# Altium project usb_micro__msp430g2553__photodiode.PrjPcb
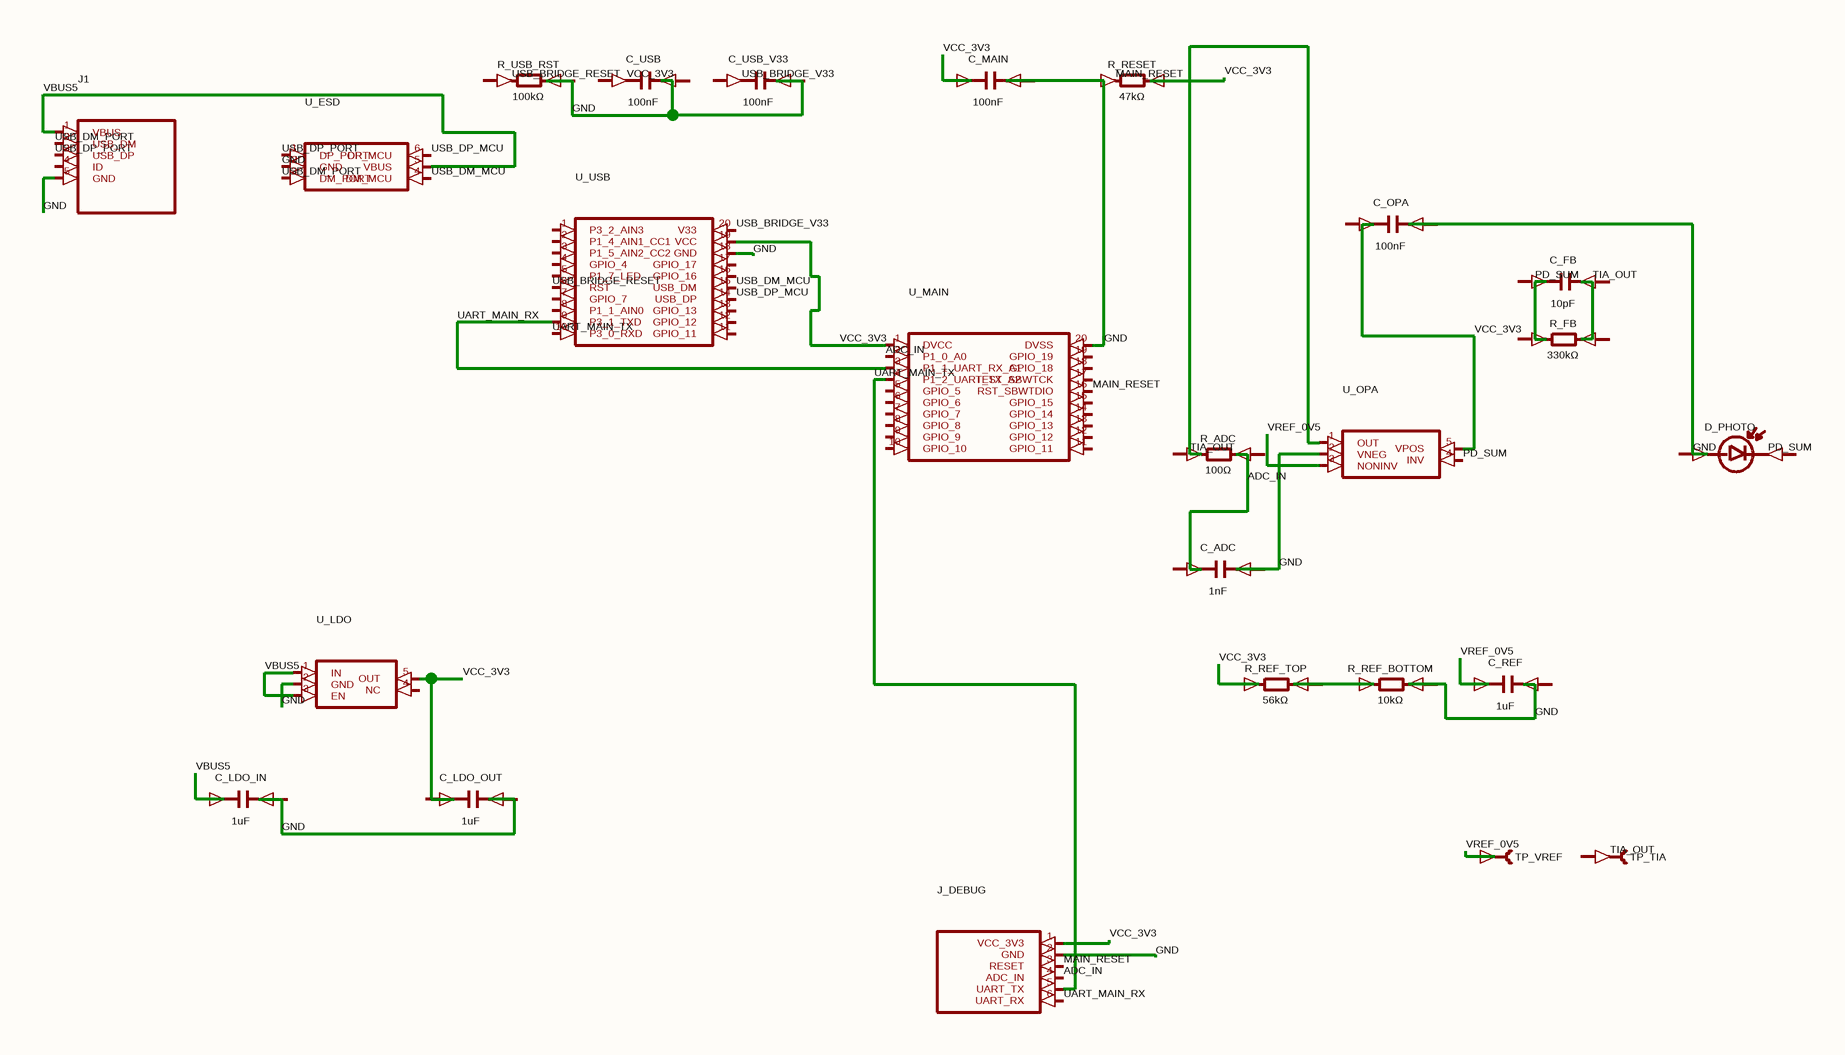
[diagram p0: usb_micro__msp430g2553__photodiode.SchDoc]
1 sheet, 25 parts. Net scope: global (net labels, ports and power ports of the same name join across sheets).
Board file: usb_micro__msp430g2553__photodiode.PcbDoc

## Sheet usb_micro__msp430g2553__photodiode.SchDoc
size 208 x 135 mm

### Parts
C_ADC  1nF
C_FB  10pF
C_LDO_IN  1uF
C_LDO_OUT  1uF
C_MAIN  100nF
C_OPA  100nF
C_REF  1uF
C_USB  100nF
C_USB_V33  100nF
D_PHOTO  (no value)
J1  (no value)
J_DEBUG  (no value)
R_ADC  100Ω
R_FB  330kΩ
R_REF_BOTTOM  10kΩ
R_REF_TOP  56kΩ
R_RESET  47kΩ
R_USB_RST  100kΩ
TP_TIA  (no value)
TP_VREF  (no value)
U_ESD  (no value)
U_LDO  (no value)
U_MAIN  (no value)
U_OPA  (no value)
U_USB  (no value)

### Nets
ADC_IN: J_DEBUG.4(ADC_IN) U_MAIN.2(P1_0_A0)
GND: C_ADC.2(neg) C_LDO_IN.1(pos) C_MAIN.1(pos) C_MAIN.2(neg) C_OPA.2(neg) J1.1(VBUS) J1.5(GND) J_DEBUG.1(VCC_3V3) J_DEBUG.2(GND) J_DEBUG.5(UART_TX) R_REF_BOTTOM.2(cathode) R_REF_TOP.1(anode) R_RESET.1(anode) R_RESET.2(cathode) U_ESD.2(GND) U_ESD.5(VBUS) U_LDO.1(IN) U_LDO.2(GND) U_LDO.3(EN) U_LDO.5(OUT) U_MAIN.1(DVCC) U_MAIN.4(P1_2_UART_TX_A2) U_MAIN.20(DVSS) U_OPA.1(OUT) U_OPA.2(VNEG) U_OPA.5(VPOS) U_USB.10(P3_0_RXD) U_USB.18(GND) U_USB.19(VCC)  [also labelled TIA_OUT, UART_MAIN_TX, VBUS5, VCC_3V3]
MAIN_RESET: J_DEBUG.3(RESET) U_MAIN.16(RST_SBWTDIO)
PD_SUM: U_OPA.4(INV)
UART_MAIN_RX: J_DEBUG.6(UART_RX) U_MAIN.3(P1_1_UART_RX_A1) U_USB.9(P3_1_TXD)
USB_BRIDGE_RESET: U_USB.6(RST)
USB_BRIDGE_V33: U_USB.20(V33)
USB_DM_MCU: U_ESD.4(DM_MCU) U_USB.15(USB_DM)
USB_DM_PORT: J1.2(USB_DM) U_ESD.3(DM_PORT)
USB_DP_MCU: U_ESD.6(DP_MCU) U_USB.14(USB_DP)
USB_DP_PORT: J1.3(USB_DP) U_ESD.1(DP_PORT)
VREF_0V5: C_REF.1(pos) TP_VREF.1(pin1) U_OPA.3(NONINV)
NetR_REF_BOTTOM_1: R_REF_BOTTOM.1(anode) R_REF_TOP.2(cathode)

Not connected (* = marked no-connect by the designer): C_ADC 1(pos); C_FB 1(pos) 2(neg); C_LDO_IN 2(neg); C_LDO_OUT 1(pos) 2(neg); C_OPA 1(pos); C_REF 2(neg); C_USB 1(pos) 2(neg); C_USB_V33 1(pos) 2(neg); D_PHOTO 1(anode) 2(cathode); J1 4(ID); R_ADC 1(anode) 2(cathode); R_FB 1(anode) 2(cathode); R_USB_RST 1(anode) 2(cathode); TP_TIA 1(pin1); U_LDO 4(NC); U_MAIN 5(GPIO_5) 6(GPIO_6) 7(GPIO_7) 8(GPIO_8) 9(GPIO_9) 10(GPIO_10) 11(GPIO_11) 12(GPIO_12) 13(GPIO_13) 14(GPIO_14) 15(GPIO_15) 17(TEST_SBWTCK) 18(GPIO_18) 19(GPIO_19); U_USB 1(P3_2_AIN3) 2(P1_4_AIN1_CC1) 3(P1_5_AIN2_CC2) 4(GPIO_4) 5(P1_7_LED) 7(GPIO_7) 8(P1_1_AIN0) 11(GPIO_11) 12(GPIO_12) 13(GPIO_13) 16(GPIO_16) 17(GPIO_17)

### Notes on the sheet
- Labels drawn without touching a wire or pin: MAIN_RESET, PD_SUM, TIA_OUT, USB_BRIDGE_RESET, USB_BRIDGE_V33, VCC_3V3

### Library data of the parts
C_ADC C_FB C_LDO_IN C_LDO_OUT C_MAIN C_OPA C_REF C_USB C_USB_V33 = capacitor_right
D_PHOTO = photodiode_horz
J1 = J1
J_DEBUG = J_DEBUG
R_ADC R_FB R_REF_BOTTOM R_REF_TOP R_RESET R_USB_RST = boxresistor_right
TP_TIA TP_VREF = testpoint_right
U_ESD = U_ESD
U_LDO = U_LDO
U_MAIN = U_MAIN
U_OPA = U_OPA
U_USB = U_USB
